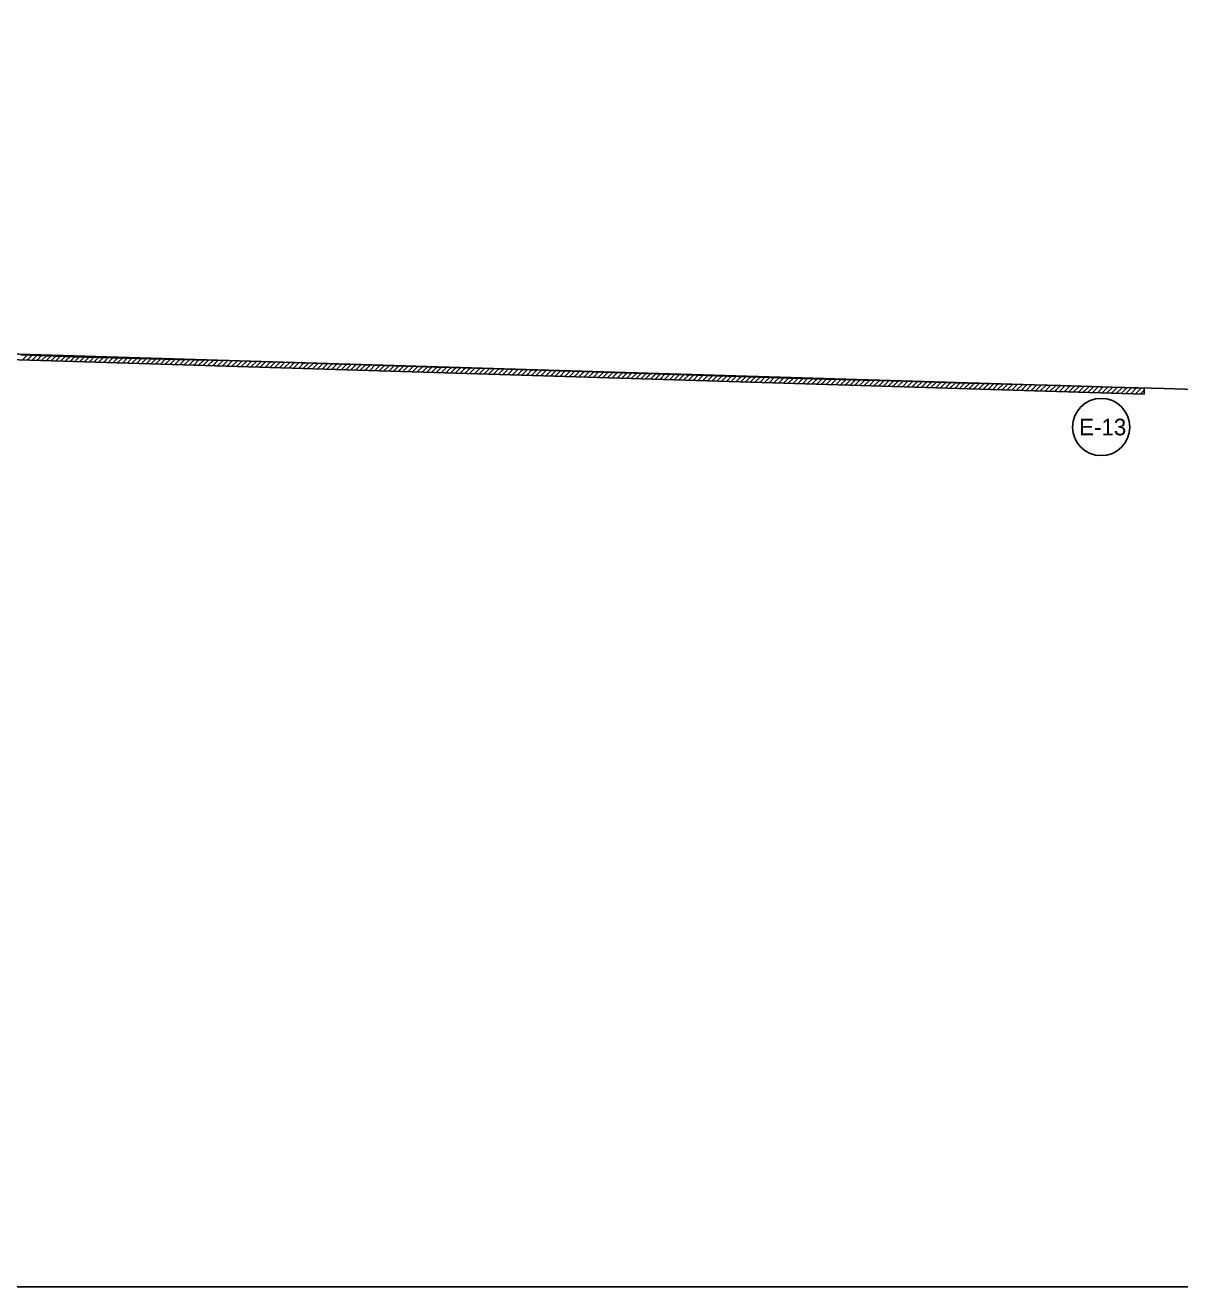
# Model space of a CAD drawing. Extents: x 976877 to 983987, y 1525984 to 1526526.
# Drawn here: x 983296.7 to 983629.8, y 1526043.8 to 1526408 of the extents above; entities that cross this region are included whole.
import ezdxf

# ---------------------------------------------------------------- set-up
doc = ezdxf.new("R2010")
doc.units = 0
doc.layers.add('R_Erosion', color=7, linetype='Continuous')
doc.layers.add('R_No Plot', color=7, linetype='Continuous')

msp = doc.modelspace()

# ---------------------------------------------------------------- linework, layer by layer
at = {"layer": 'R_Erosion'}
for p, q in [((982980.7, 1526322.43), (983619.57, 1526303.24)), ((983619.52, 1526301.48), (982980.66, 1526320.94)), ((983295.89, 1526311.33), (983297.47, 1526312.92)), ((983297.26, 1526311.29), (983298.84, 1526312.87)), ((983298.63, 1526311.25), (983300.21, 1526312.83)), ((983300, 1526311.21), (983301.59, 1526312.79)), ((983301.38, 1526311.17), (983302.96, 1526312.75)), ((983302.75, 1526311.13), (983304.33, 1526312.71)), ((983304.12, 1526311.08), (983305.71, 1526312.67)), ((983305.49, 1526311.04), (983307.08, 1526312.63)), ((983306.87, 1526311), (983308.45, 1526312.59)), ((983308.24, 1526310.96), (983309.82, 1526312.54)), ((983309.61, 1526310.92), (983311.2, 1526312.5)), ((983310.98, 1526310.87), (983312.57, 1526312.46)), ((983312.36, 1526310.83), (983313.94, 1526312.42)), ((983313.73, 1526310.79), (983315.32, 1526312.38)), ((983315.1, 1526310.75), (983316.69, 1526312.34)), ((983316.47, 1526310.71), (983318.06, 1526312.3)), ((983317.85, 1526310.67), (983319.44, 1526312.26)), ((983319.22, 1526310.62), (983320.81, 1526312.21)), ((983320.59, 1526310.58), (983322.18, 1526312.17)), ((983321.96, 1526310.54), (983323.55, 1526312.13)), ((983323.33, 1526310.5), (983324.93, 1526312.09)), ((983324.71, 1526310.46), (983326.3, 1526312.05)), ((983326.08, 1526310.42), (983327.67, 1526312.01)), ((983327.45, 1526310.37), (983329.05, 1526311.97)), ((983328.82, 1526310.33), (983330.42, 1526311.93)), ((983330.2, 1526310.29), (983331.79, 1526311.88)), ((983331.57, 1526310.25), (983333.16, 1526311.84)), ((983332.94, 1526310.21), (983334.54, 1526311.8)), ((983334.31, 1526310.16), (983335.91, 1526311.76)), ((983335.69, 1526310.12), (983337.28, 1526311.72)), ((983337.06, 1526310.08), (983338.66, 1526311.68)), ((983338.43, 1526310.04), (983340.03, 1526311.64)), ((983339.8, 1526310), (983341.4, 1526311.6)), ((983341.18, 1526309.96), (983342.78, 1526311.55)), ((983342.55, 1526309.91), (983344.15, 1526311.51)), ((983343.92, 1526309.87), (983345.52, 1526311.47)), ((983345.29, 1526309.83), (983346.89, 1526311.43)), ((983346.67, 1526309.79), (983348.27, 1526311.39)), ((983348.04, 1526309.75), (983349.64, 1526311.35)), ((983349.41, 1526309.7), (983351.01, 1526311.31)), ((983350.78, 1526309.66), (983352.39, 1526311.27)), ((983352.16, 1526309.62), (983353.76, 1526311.22)), ((983353.53, 1526309.58), (983355.13, 1526311.18)), ((983354.9, 1526309.54), (983356.51, 1526311.14)), ((983356.27, 1526309.5), (983357.88, 1526311.1)), ((983357.65, 1526309.45), (983359.25, 1526311.06)), ((983359.02, 1526309.41), (983360.62, 1526311.02)), ((983360.39, 1526309.37), (983362, 1526310.98)), ((983361.76, 1526309.33), (983363.37, 1526310.94)), ((983363.13, 1526309.29), (983364.74, 1526310.89)), ((983364.51, 1526309.24), (983366.12, 1526310.85)), ((983365.88, 1526309.2), (983367.49, 1526310.81)), ((983367.25, 1526309.16), (983368.86, 1526310.77)), ((983368.62, 1526309.12), (983370.23, 1526310.73)), ((983370, 1526309.08), (983371.61, 1526310.69)), ((983371.37, 1526309.04), (983372.98, 1526310.65)), ((983372.74, 1526308.99), (983374.35, 1526310.61)), ((983374.11, 1526308.95), (983375.73, 1526310.56)), ((983375.49, 1526308.91), (983377.1, 1526310.52)), ((983376.86, 1526308.87), (983378.47, 1526310.48)), ((983378.23, 1526308.83), (983379.85, 1526310.44)), ((983379.6, 1526308.79), (983381.22, 1526310.4)), ((983380.98, 1526308.74), (983382.59, 1526310.36)), ((983382.35, 1526308.7), (983383.96, 1526310.32)), ((983383.72, 1526308.66), (983385.34, 1526310.28)), ((983385.09, 1526308.62), (983386.71, 1526310.23)), ((983386.47, 1526308.58), (983388.08, 1526310.19)), ((983387.84, 1526308.53), (983389.46, 1526310.15)), ((983389.21, 1526308.49), (983390.83, 1526310.11)), ((983390.58, 1526308.45), (983392.2, 1526310.07)), ((983391.96, 1526308.41), (983393.58, 1526310.03)), ((983393.33, 1526308.37), (983394.95, 1526309.99)), ((983394.7, 1526308.33), (983396.32, 1526309.95)), ((983396.07, 1526308.28), (983397.69, 1526309.9)), ((983397.45, 1526308.24), (983399.07, 1526309.86)), ((983398.82, 1526308.2), (983400.44, 1526309.82)), ((983400.19, 1526308.16), (983401.81, 1526309.78)), ((983401.56, 1526308.12), (983403.19, 1526309.74)), ((983402.93, 1526308.07), (983404.56, 1526309.7)), ((983404.31, 1526308.03), (983405.93, 1526309.66)), ((983405.68, 1526307.99), (983407.3, 1526309.62)), ((983407.05, 1526307.95), (983408.68, 1526309.57)), ((983408.42, 1526307.91), (983410.05, 1526309.53)), ((983409.8, 1526307.87), (983411.42, 1526309.49)), ((983411.17, 1526307.82), (983412.8, 1526309.45)), ((983412.54, 1526307.78), (983414.17, 1526309.41)), ((983413.91, 1526307.74), (983415.54, 1526309.37)), ((983415.29, 1526307.7), (983416.92, 1526309.33)), ((983416.66, 1526307.66), (983418.29, 1526309.29)), ((983418.03, 1526307.61), (983419.66, 1526309.24)), ((983419.4, 1526307.57), (983421.03, 1526309.2)), ((983420.78, 1526307.53), (983422.41, 1526309.16)), ((983422.15, 1526307.49), (983423.78, 1526309.12)), ((983423.52, 1526307.45), (983425.15, 1526309.08)), ((983424.89, 1526307.41), (983426.53, 1526309.04)), ((983426.27, 1526307.36), (983427.9, 1526309)), ((983427.64, 1526307.32), (983429.27, 1526308.96)), ((983429.01, 1526307.28), (983430.64, 1526308.91)), ((983430.38, 1526307.24), (983432.02, 1526308.87)), ((983431.76, 1526307.2), (983433.39, 1526308.83)), ((983433.13, 1526307.16), (983434.76, 1526308.79)), ((983434.5, 1526307.11), (983436.14, 1526308.75)), ((983435.87, 1526307.07), (983437.51, 1526308.71)), ((983437.25, 1526307.03), (983438.88, 1526308.67)), ((983438.62, 1526306.99), (983440.26, 1526308.63)), ((983439.99, 1526306.95), (983441.63, 1526308.58)), ((983441.36, 1526306.9), (983443, 1526308.54)), ((983442.74, 1526306.86), (983444.37, 1526308.5)), ((983444.11, 1526306.82), (983445.75, 1526308.46)), ((983445.48, 1526306.78), (983447.12, 1526308.42)), ((983446.85, 1526306.74), (983448.49, 1526308.38)), ((983448.22, 1526306.7), (983449.87, 1526308.34)), ((983449.6, 1526306.65), (983451.24, 1526308.3)), ((983450.97, 1526306.61), (983452.61, 1526308.25)), ((983452.34, 1526306.57), (983453.99, 1526308.21)), ((983453.71, 1526306.53), (983455.36, 1526308.17)), ((983455.09, 1526306.49), (983456.73, 1526308.13)), ((983456.46, 1526306.44), (983458.1, 1526308.09)), ((983457.83, 1526306.4), (983459.48, 1526308.05)), ((983459.2, 1526306.36), (983460.85, 1526308.01)), ((983460.58, 1526306.32), (983462.22, 1526307.97)), ((983461.95, 1526306.28), (983463.6, 1526307.92)), ((983463.32, 1526306.24), (983464.97, 1526307.88)), ((983464.69, 1526306.19), (983466.34, 1526307.84)), ((983466.07, 1526306.15), (983467.71, 1526307.8)), ((983467.44, 1526306.11), (983469.09, 1526307.76)), ((983468.81, 1526306.07), (983470.46, 1526307.72)), ((983470.18, 1526306.03), (983471.83, 1526307.68)), ((983471.56, 1526305.98), (983473.21, 1526307.64)), ((983472.93, 1526305.94), (983474.58, 1526307.59)), ((983474.3, 1526305.9), (983475.95, 1526307.55)), ((983475.67, 1526305.86), (983477.33, 1526307.51)), ((983477.05, 1526305.82), (983478.7, 1526307.47)), ((983478.42, 1526305.78), (983480.07, 1526307.43)), ((983479.79, 1526305.73), (983481.44, 1526307.39)), ((983481.16, 1526305.69), (983482.82, 1526307.35)), ((983482.54, 1526305.65), (983484.19, 1526307.31)), ((983483.91, 1526305.61), (983485.56, 1526307.26)), ((983485.28, 1526305.57), (983486.94, 1526307.22)), ((983486.65, 1526305.52), (983488.31, 1526307.18)), ((983488.02, 1526305.48), (983489.68, 1526307.14)), ((983489.4, 1526305.44), (983491.06, 1526307.1)), ((983490.77, 1526305.4), (983492.43, 1526307.06)), ((983492.14, 1526305.36), (983493.8, 1526307.02)), ((983493.51, 1526305.32), (983495.17, 1526306.98)), ((983494.89, 1526305.27), (983496.55, 1526306.93)), ((983496.26, 1526305.23), (983497.92, 1526306.89)), ((983497.63, 1526305.19), (983499.29, 1526306.85)), ((983499, 1526305.15), (983500.67, 1526306.81)), ((983500.38, 1526305.11), (983502.04, 1526306.77)), ((983501.75, 1526305.07), (983503.41, 1526306.73)), ((983503.12, 1526305.02), (983504.78, 1526306.69)), ((983504.49, 1526304.98), (983506.16, 1526306.65)), ((983505.87, 1526304.94), (983507.53, 1526306.6)), ((983507.24, 1526304.9), (983508.9, 1526306.56)), ((983508.61, 1526304.86), (983510.28, 1526306.52)), ((983509.98, 1526304.81), (983511.65, 1526306.48)), ((983511.36, 1526304.77), (983513.02, 1526306.44)), ((983512.73, 1526304.73), (983514.4, 1526306.4)), ((983514.1, 1526304.69), (983515.77, 1526306.36)), ((983515.47, 1526304.65), (983517.14, 1526306.32)), ((983516.85, 1526304.61), (983518.51, 1526306.27)), ((983518.22, 1526304.56), (983519.89, 1526306.23)), ((983519.59, 1526304.52), (983521.26, 1526306.19)), ((983520.96, 1526304.48), (983522.63, 1526306.15)), ((983522.34, 1526304.44), (983524.01, 1526306.11)), ((983523.71, 1526304.4), (983525.38, 1526306.07)), ((983525.08, 1526304.35), (983526.75, 1526306.03)), ((983526.45, 1526304.31), (983528.12, 1526305.99)), ((983527.82, 1526304.27), (983529.5, 1526305.94)), ((983529.2, 1526304.23), (983530.87, 1526305.9)), ((983530.57, 1526304.19), (983532.24, 1526305.86)), ((983531.94, 1526304.15), (983533.62, 1526305.82)), ((983533.31, 1526304.1), (983534.99, 1526305.78)), ((983534.69, 1526304.06), (983536.36, 1526305.74)), ((983536.06, 1526304.02), (983537.74, 1526305.7)), ((983537.43, 1526303.98), (983539.11, 1526305.66)), ((983538.8, 1526303.94), (983540.48, 1526305.61)), ((983540.18, 1526303.89), (983541.85, 1526305.57)), ((983541.55, 1526303.85), (983543.23, 1526305.53)), ((983542.92, 1526303.81), (983544.6, 1526305.49)), ((983544.29, 1526303.77), (983545.97, 1526305.45)), ((983545.67, 1526303.73), (983547.35, 1526305.41)), ((983547.04, 1526303.69), (983548.72, 1526305.37)), ((983548.41, 1526303.64), (983550.09, 1526305.33)), ((983549.78, 1526303.6), (983551.47, 1526305.28)), ((983551.16, 1526303.56), (983552.84, 1526305.24)), ((983552.53, 1526303.52), (983554.21, 1526305.2)), ((983553.9, 1526303.48), (983555.58, 1526305.16)), ((983555.27, 1526303.44), (983556.96, 1526305.12)), ((983556.65, 1526303.39), (983558.33, 1526305.08)), ((983558.02, 1526303.35), (983559.7, 1526305.04)), ((983559.39, 1526303.31), (983561.08, 1526305)), ((983560.76, 1526303.27), (983562.45, 1526304.95)), ((983562.14, 1526303.23), (983563.82, 1526304.91)), ((983563.51, 1526303.18), (983565.19, 1526304.87)), ((983564.88, 1526303.14), (983566.57, 1526304.83)), ((983566.25, 1526303.1), (983567.94, 1526304.79)), ((983567.62, 1526303.06), (983569.31, 1526304.75)), ((983569, 1526303.02), (983570.69, 1526304.71)), ((983570.37, 1526302.98), (983572.06, 1526304.67)), ((983571.74, 1526302.93), (983573.43, 1526304.62)), ((983573.11, 1526302.89), (983574.81, 1526304.58)), ((983574.49, 1526302.85), (983576.18, 1526304.54)), ((983575.86, 1526302.81), (983577.55, 1526304.5)), ((983577.23, 1526302.77), (983578.92, 1526304.46)), ((983578.6, 1526302.72), (983580.3, 1526304.42)), ((983579.98, 1526302.68), (983581.67, 1526304.38)), ((983581.35, 1526302.64), (983583.04, 1526304.34)), ((983582.72, 1526302.6), (983584.42, 1526304.29)), ((983584.09, 1526302.56), (983585.79, 1526304.25)), ((983585.47, 1526302.52), (983587.16, 1526304.21)), ((983586.84, 1526302.47), (983588.54, 1526304.17)), ((983588.21, 1526302.43), (983589.91, 1526304.13)), ((983589.58, 1526302.39), (983591.28, 1526304.09)), ((983590.96, 1526302.35), (983592.65, 1526304.05)), ((983592.33, 1526302.31), (983594.03, 1526304.01)), ((983593.7, 1526302.26), (983595.4, 1526303.96)), ((983595.07, 1526302.22), (983596.77, 1526303.92)), ((983596.45, 1526302.18), (983598.15, 1526303.88)), ((983597.82, 1526302.14), (983599.52, 1526303.84)), ((983599.19, 1526302.1), (983600.89, 1526303.8)), ((983600.56, 1526302.06), (983602.26, 1526303.76)), ((983601.94, 1526302.01), (983603.64, 1526303.72)), ((983603.31, 1526301.97), (983605.01, 1526303.68)), ((983604.68, 1526301.93), (983606.38, 1526303.63)), ((983606.05, 1526301.89), (983607.76, 1526303.59)), ((983607.43, 1526301.85), (983609.13, 1526303.55)), ((983608.8, 1526301.81), (983610.5, 1526303.51)), ((983610.17, 1526301.76), (983611.88, 1526303.47)), ((983611.54, 1526301.72), (983613.25, 1526303.43)), ((983612.91, 1526301.68), (983614.62, 1526303.39)), ((983614.29, 1526301.64), (983615.99, 1526303.35)), ((983615.66, 1526301.6), (983617.37, 1526303.3)), ((983617.03, 1526301.55), (983618.74, 1526303.26)), ((983618.4, 1526301.51), (983619.55, 1526302.66)), ((983619.57, 1526303.24), (983619.52, 1526301.48))]:
    msp.add_line(p, q, dxfattribs=at)
msp.add_circle((983607.15, 1526291.98), 8.26, dxfattribs=at)
at = {"layer": 'R_No Plot'}
for points in [[(980311.86, 1526407.98), (980311.86, 1526043.76), (983987.45, 1526043.76), (983987.45, 1526292.17)], [(983640.33, 1526302.61), (983625.34, 1526303.08), (983610.35, 1526303.45), (983595.36, 1526303.92), (983580.37, 1526304.32), (983565.38, 1526304.78), (983550.38, 1526305.21), (983535.39, 1526305.6), (983520.33, 1526305.99), (983505.34, 1526306.51), (983490.35, 1526306.99), (983460.36, 1526307.91), (983445.37, 1526308.38), (983430.41, 1526308.85), (983415.42, 1526309.28), (983400.43, 1526309.74), (983385.43, 1526310.21), (983370.44, 1526310.66), (983355.45, 1526311.15), (983340.46, 1526311.52), (983325.45, 1526311.86), (983310.46, 1526312.28), (983295.47, 1526312.78)]]:
    msp.add_lwpolyline(points, dxfattribs=at)
msp.add_circle((983607.15, 1526291.98), 8.26, dxfattribs=at)

# ---------------------------------------------------------------- texts
at = {"layer": 'R_Erosion'}
msp.add_text('E-13', height=4.8, dxfattribs=at).set_placement((983600.82, 1526289.58))

doc.saveas('drawing.dxf')
